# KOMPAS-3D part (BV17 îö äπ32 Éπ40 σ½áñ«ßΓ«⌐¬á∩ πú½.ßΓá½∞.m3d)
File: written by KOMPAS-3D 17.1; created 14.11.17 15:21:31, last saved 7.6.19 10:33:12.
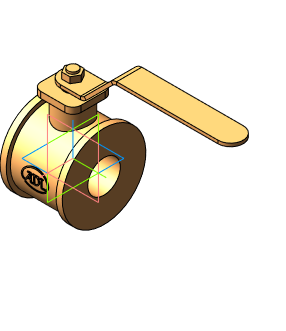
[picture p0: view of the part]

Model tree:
1. Операция без истории:1  (labels: Сталь 20  ГОСТ 1050-2013)

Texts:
  Линейный размер с обрывом
  Толщина листового тела
  Глубина освобождения сгиба
  Ширина освобождения сгиба
  BV17 МФ Ду15 Ру40 хладостойкая угл.сталь
  BV17 МФ Ду20 Ру40 хладостойкая угл.сталь
  BV17 МФ Ду25 Ру40 хладостойкая угл.сталь
  BV17 МФ Ду32 Ру40 хладостойкая угл.сталь
  BV17 МФ Ду40 Ру40 хладостойкая угл.сталь
  BV17 МФ Ду50 Ру40 хладостойкая угл.сталь
  BV17 МФ Ду65 Ру40 хладостойкая угл.сталь
  BV17 МФ Ду80 Ру40 хладостойкая угл.сталь
  BV17 МФ Ду100 Ру40 хладостойкая угл.сталь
